Omron CX-Programmer project CP1H_Y20DT_D (CX-Programmer 8.20)
; CP1H-Y20DT-D Demo with R7D-BP01L & NP3-MQ000B

# PLC NewPLC1: CP1H Y

## Global symbols (name address type ; comment)
Acceleration D104 INT  ; Acceleration Hz/4ms
AlarmOutput 0.00 BOOL  ; When the Servo Drive generates an alarm, the output turns OFF.
AlarmResetInput 100.05 BOOL  ; $?St$Bk?_#[117] / ON: Servo alarm status is reset. / Must be ON for 120 ms min.$?St$Bk?_#[117]
101.02 BOOL  ; Origin search 0 (Error counter reset output)
1.03 BOOL  ; Pulse output 0: Origin input signal (open collector)
1.05 BOOL  ; Pulse output 0: Origin proximity input signal
A274.00 BOOL  ; $?St$Bk?_#[118] / Range Comparison Condition Met Flag / Range 1 Comparison Condition Met Flag$?St$Bk?_#[118]
A274.08 BOOL  ; $?St$Bk?_#[119] / Comparison In progress Flag / ON when a comparison operation is being executed for the high-speed counter$?St$Bk?_#[119]
A274.09 BOOL  ; $?St$Bk?_#[120] / Overflow/Underflow Flag / ON when an overflow or underflow has occurred in the high-speed counter’s PV. (Used only when the counting mode is set to Linear Mode)$?St$Bk?_#[120]
A274.10 BOOL  ; $?St$Bk?_#[121] / Count Direction Flag / 0: Decrementing / 1: Incrementing$?St$Bk?_#[121]
A280.00 BOOL  ; $?St$Bk?_#[122] / Accel/Decel Flags / ON when pulses are being output according to an ACC(888) or PLS2(887) instruction and the output frequency is being changed in steps (accelerating or decelerating) / 0: Constant speed / 1: Accelerating or decelerating$?St$Bk?_#[122]
A280.01 BOOL  ; $?St$Bk?_#[123] / Overflow/Underflow Flags / ON when an overflow or underflow has / occurred in the pulse output PV / 0: Normal / 1: Overflow or underflow$?St$Bk?_#[123]
A280.02 BOOL  ; $?St$Bk?_#[124] / Output Amount Set Flags / ON when the number of output pulses has been set with the PULS instruction / 0: No setting / 1: Setting made$?St$Bk?_#[124]
A280.03 BOOL  ; $?St$Bk?_#[125] / Output Completed Flags / ON when the number of output pulses set with the PULS(886)/PLS2(887) instruction has been output / 0: Output not completed / 1: Output completed$?St$Bk?_#[125]
A280.04 BOOL  ; $?St$Bk?_#[126] / Output In-progress Flags / ON when pulses are being output from the pulse output / 0: Stopped / 1: Outputting pulses$?St$Bk?_#[126]
A280.05 BOOL  ; $?St$Bk?_#[127] / No-origin Flags / ON when the origin has not been determined for the pulse output / 0: Origin established / 1: Origin not established$?St$Bk?_#[127]
A280.06 BOOL  ; $?St$Bk?_#[128] / At-origin Flags / ON when the pulse output PV matches / the origin (0) / 0: Not stopped at origin / 1: Stopped at origin$?St$Bk?_#[128]
A280.07 BOOL  ; $?St$Bk?_#[129] / Output Stopped Error Flags / ON when an error occurred while outputting pulses in the origin search function / 0: No error / 1: Stop error occurred$?St$Bk?_#[129]
A392.12 BOOL  ; $?St$Bk?_#[130] / Peripheral Port Communications / Error Flag / ON when a communications error has occurred at the serial port 1$?St$Bk?_#[130]
A444 CHANNEL  ; Stop Error Codes
A526.01 BOOL  ; $?St$Bk?_#[131] / Peripheral Port Restart Bit / Turn this bit ON to restart the serial port 1$?St$Bk?_#[131]
A531.00 BOOL  ; $?St$Bk?_#[132] / Reset Bit / Used for the PV software reset$?St$Bk?_#[132]
A540.00 BOOL  ; $?St$Bk?_#[134] / Reset Bits / The pulse output PV will be cleared when this bit is turned from OFF to ON / 0: Not cleared / 1: Clear PV$?St$Bk?_#[134]
D10 CHANNEL  ; PLS2 Acceleration
D11 CHANNEL  ; PLS2 Deceleration
D12 CHANNEL  ; PLS2 Move Speed
D14 CHANNEL  ; PLS2 Position
H0 CHANNEL  ; PT Control Block
H10 CHANNEL  ; PT Status Block
W0.00 BOOL  ; Reset Alarm
W0.08 BOOL  ; Reset Alarm Required
W10.00 BOOL  ; Servo Alarm
W10.01 BOOL  ; Servo Warning
W11.00 BOOL  ; Origin Servo
W1.00 BOOL  ; Origin Search
W1.01 BOOL  ; Origin Return
W1.02 BOOL  ; Jog Forward
W1.03 BOOL  ; Jog Reverse
W1.04 BOOL  ; Absolute Move
W1.05 BOOL  ; Start Move
W1.06 BOOL  ; Stop Move
W2.00 BOOL  ; Origin Search Latch
W2.01 BOOL  ; Origin Return Latch
W2.04 BOOL  ; Absolute Move One Shot
W3.00 BOOL  ; Origin Search Executing
W3.01 BOOL  ; Origin Return Executing
W3.02 BOOL  ; Jog Forward Executing
W3.03 BOOL  ; Jog Reverse Executing
W3.04 BOOL  ; Absolute Move Enabled
W3.05 BOOL  ; Move Executing
W3.06 BOOL  ; Stop Move
W4.00 BOOL  ; Commanded Position Was Positive
BrakeInterlockOutput 0.04 BOOL  ; Outputs the holding brake timing signals. Release the holding brake when this signal is ON.
Deceleration D105 INT  ; Deceleration Hz/4ms
DeviationCounterResetInput 100.06 BOOL  ; $?St$Bk?_#[138] / Deviation Counter Reset Input in Position Control Mode (when Pn02 is set to 0 or 2). / ON: Pulse commands prohibited and deviation counter cleared. Must be ON for at least 2 ms.$?St$Bk?_#[138]
ElectronicGearSwitchInput 101.00 BOOL  ; $?St$Bk?_#[139] / Electronic Gear Switch Input in Position Control Mode (when Pn02 is set to 0 or 2). / OFF: Electronic Gear Ratio Numerator 1 (Pn46) / ON: Electronic Gear Ratio Numerator 2 (Pn47)$?St$Bk?_#[139]
GainSwitchInput 100.07 BOOL  ; Gain Switch Input in Position Control Mode (when Pn02 is set to 0 or 2) when Zero Speed Designation/Torque Limit Switch (Pn06) is set to 0 or 1.
HighSpeedCounter A270 DINT  ; High-speed Counter PV
JogRunSpeedReference D0 UDINT  ; Jog Run Speed Reference
JogStopSpeedReference D2 UDINT  ; Jog Stop Speed Reference
MoveSpeed D102 DINT  ; Move Speed In Degrees/Second
Position D100 DINT  ; Position In Degrees
PositioningCompletedOutput 0.01 BOOL  ; $?St$Bk?_#[140] / Positioning completed output in Position Control Mode (when Pn02 is set to 0 or 2). / ON: The residual pulses for the deviation counter are within the setting for Positioning Completion Range (Pn60).$?St$Bk?_#[140]
PulseOutput A276 DINT  ; Pulse Output PV
RunCommandInput 100.04 BOOL  ; ON: Servo ON (Starts power to Servomotor.)
WarningOutput 0.05 BOOL  ; The signal selected in the Warning Output Selection (Pn09) is output.

## Program NewProgram1 (cyclic task 0)

### Section Main

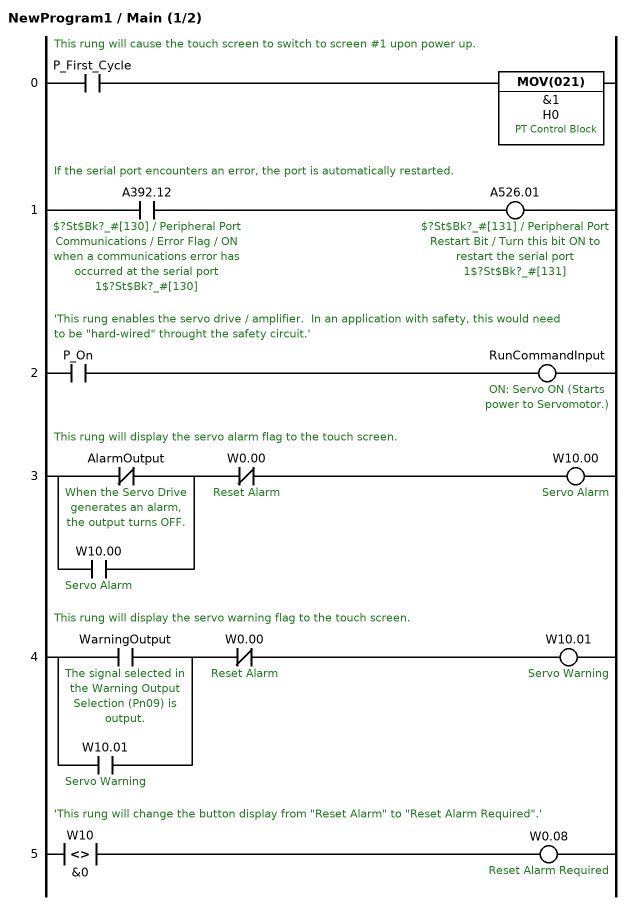
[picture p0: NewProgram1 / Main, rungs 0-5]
; rung 0: This rung will cause the touch screen to switch to screen #1 upon power up.
LD P_First_Cycle
MOV(021) &1 H0  ; PT Control Block
; rung 1: If the serial port encounters an error, the port is automatically restarted.
LD A392.12  ; $?St$Bk?_#[130] / Peripheral Port Communications / Error Flag / ON when a communications error has occurred at the serial port 1$?St$Bk?_#[130]
OUT A526.01  ; $?St$Bk?_#[131] / Peripheral Port Restart Bit / Turn this bit ON to restart the serial port 1$?St$Bk?_#[131]
; rung 2: 'This rung enables the servo drive / amplifier.  In an application with safety, this would need to be "hard-wired" throught the safety circuit.'
LD P_On
OUT RunCommandInput  ; ON: Servo ON (Starts power to Servomotor.)
; rung 3: This rung will display the servo alarm flag to the touch screen.
LDNOT AlarmOutput  ; When the Servo Drive generates an alarm, the output turns OFF.
OR W10.00  ; Servo Alarm
ANDNOT W0.00  ; Reset Alarm
OUT W10.00  ; Servo Alarm
; rung 4: This rung will display the servo warning flag to the touch screen.
LD WarningOutput  ; The signal selected in the Warning Output Selection (Pn09) is output.
OR W10.01  ; Servo Warning
ANDNOT W0.00  ; Reset Alarm
OUT W10.01  ; Servo Warning
; rung 5: 'This rung will change the button display from "Reset Alarm" to "Reset Alarm Required".'
LD<>(305) W10 &0
OUT W0.08  ; Reset Alarm Required

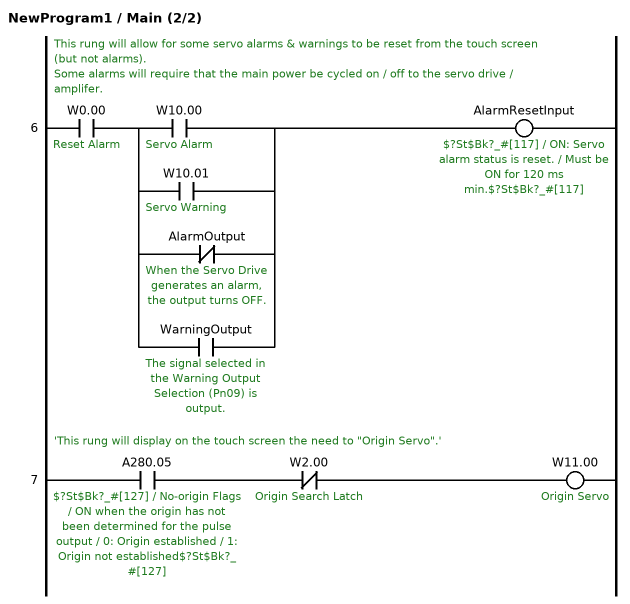
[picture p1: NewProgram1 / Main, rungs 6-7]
; rung 6: This rung will allow for some servo alarms & warnings to be reset from the touch screen (but not alarms). / Some alarms will require that the main power be cycled on / off to the servo drive / amplifer.
LD W0.00  ; Reset Alarm
LD W10.00  ; Servo Alarm
OR W10.01  ; Servo Warning
ORNOT AlarmOutput  ; When the Servo Drive generates an alarm, the output turns OFF.
OR WarningOutput  ; The signal selected in the Warning Output Selection (Pn09) is output.
ANDLD
OUT AlarmResetInput  ; $?St$Bk?_#[117] / ON: Servo alarm status is reset. / Must be ON for 120 ms min.$?St$Bk?_#[117]
; rung 7: 'This rung will display on the touch screen the need to "Origin Servo".'
LD A280.05  ; $?St$Bk?_#[127] / No-origin Flags / ON when the origin has not been determined for the pulse output / 0: Origin established / 1: Origin not established$?St$Bk?_#[127]
ANDNOT W2.00  ; Origin Search Latch
OUT W11.00  ; Origin Servo

### Section Origin

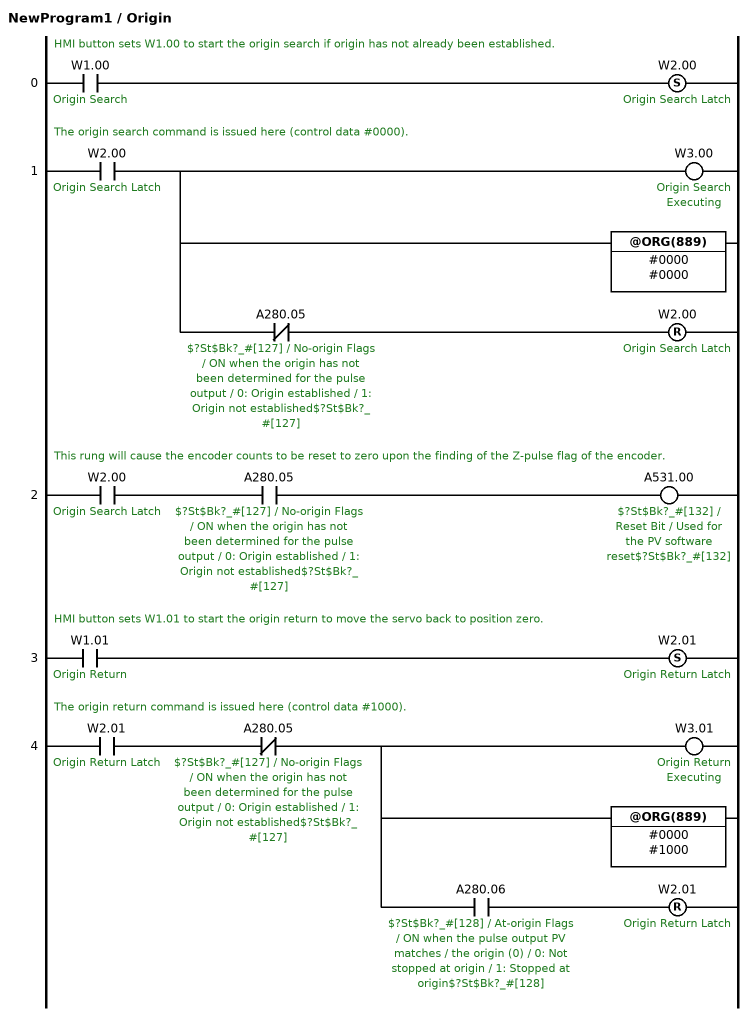
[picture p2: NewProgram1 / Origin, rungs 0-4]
; rung 0: HMI button sets W1.00 to start the origin search if origin has not already been established.
LD W1.00  ; Origin Search
SET W2.00  ; Origin Search Latch
; rung 1: The origin search command is issued here (control data #0000).
LD W2.00  ; Origin Search Latch
OUT W3.00  ; Origin Search Executing
@ORG(889) #0000 #0000
ANDNOT A280.05  ; $?St$Bk?_#[127] / No-origin Flags / ON when the origin has not been determined for the pulse output / 0: Origin established / 1: Origin not established$?St$Bk?_#[127]
RSET W2.00  ; Origin Search Latch
; rung 2: This rung will cause the encoder counts to be reset to zero upon the finding of the Z-pulse flag of the encoder.
LD W2.00  ; Origin Search Latch
AND A280.05  ; $?St$Bk?_#[127] / No-origin Flags / ON when the origin has not been determined for the pulse output / 0: Origin established / 1: Origin not established$?St$Bk?_#[127]
OUT A531.00  ; $?St$Bk?_#[132] / Reset Bit / Used for the PV software reset$?St$Bk?_#[132]
; rung 3: HMI button sets W1.01 to start the origin return to move the servo back to position zero.
LD W1.01  ; Origin Return
SET W2.01  ; Origin Return Latch
; rung 4: The origin return command is issued here (control data #1000).
LD W2.01  ; Origin Return Latch
ANDNOT A280.05  ; $?St$Bk?_#[127] / No-origin Flags / ON when the origin has not been determined for the pulse output / 0: Origin established / 1: Origin not established$?St$Bk?_#[127]
OUT W3.01  ; Origin Return Executing
@ORG(889) #0000 #1000
AND A280.06  ; $?St$Bk?_#[128] / At-origin Flags / ON when the pulse output PV matches / the origin (0) / 0: Not stopped at origin / 1: Stopped at origin$?St$Bk?_#[128]
RSET W2.01  ; Origin Return Latch

### Section Jog

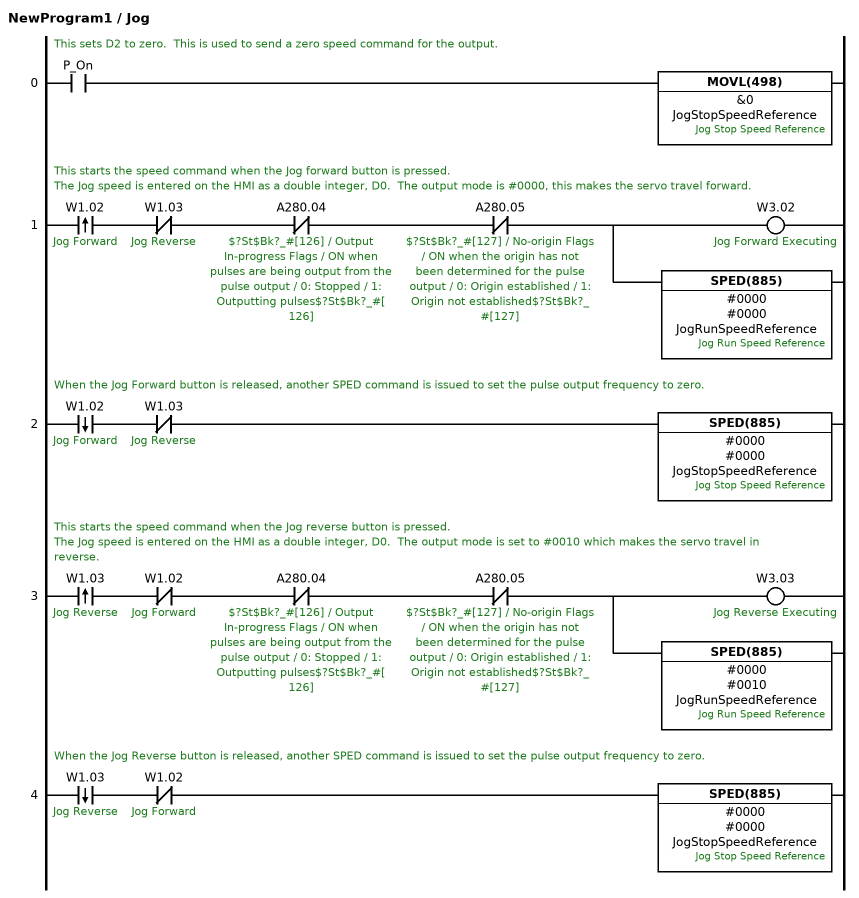
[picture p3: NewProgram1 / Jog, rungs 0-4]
; rung 0: This sets D2 to zero.  This is used to send a zero speed command for the output.
LD P_On
MOVL(498) &0 JogStopSpeedReference  ; Jog Stop Speed Reference
; rung 1: This starts the speed command when the Jog forward button is pressed. / The Jog speed is entered on the HMI as a double integer, D0.  The output mode is #0000, this makes the servo travel forward.
@LD W1.02  ; Jog Forward
ANDNOT W1.03  ; Jog Reverse
ANDNOT A280.04  ; $?St$Bk?_#[126] / Output In-progress Flags / ON when pulses are being output from the pulse output / 0: Stopped / 1: Outputting pulses$?St$Bk?_#[126]
ANDNOT A280.05  ; $?St$Bk?_#[127] / No-origin Flags / ON when the origin has not been determined for the pulse output / 0: Origin established / 1: Origin not established$?St$Bk?_#[127]
OUT W3.02  ; Jog Forward Executing
SPED(885) #0000 #0000 JogRunSpeedReference  ; Jog Run Speed Reference
; rung 2: When the Jog Forward button is released, another SPED command is issued to set the pulse output frequency to zero.
%LD W1.02  ; Jog Forward
ANDNOT W1.03  ; Jog Reverse
SPED(885) #0000 #0000 JogStopSpeedReference  ; Jog Stop Speed Reference
; rung 3: This starts the speed command when the Jog reverse button is pressed. / The Jog speed is entered on the HMI as a double integer, D0.  The output mode is set to #0010 which makes the servo travel in reverse.
@LD W1.03  ; Jog Reverse
ANDNOT W1.02  ; Jog Forward
ANDNOT A280.04  ; $?St$Bk?_#[126] / Output In-progress Flags / ON when pulses are being output from the pulse output / 0: Stopped / 1: Outputting pulses$?St$Bk?_#[126]
ANDNOT A280.05  ; $?St$Bk?_#[127] / No-origin Flags / ON when the origin has not been determined for the pulse output / 0: Origin established / 1: Origin not established$?St$Bk?_#[127]
OUT W3.03  ; Jog Reverse Executing
SPED(885) #0000 #0010 JogRunSpeedReference  ; Jog Run Speed Reference
; rung 4: When the Jog Reverse button is released, another SPED command is issued to set the pulse output frequency to zero.
%LD W1.03  ; Jog Reverse
ANDNOT W1.02  ; Jog Forward
SPED(885) #0000 #0000 JogStopSpeedReference  ; Jog Stop Speed Reference

### Section Move

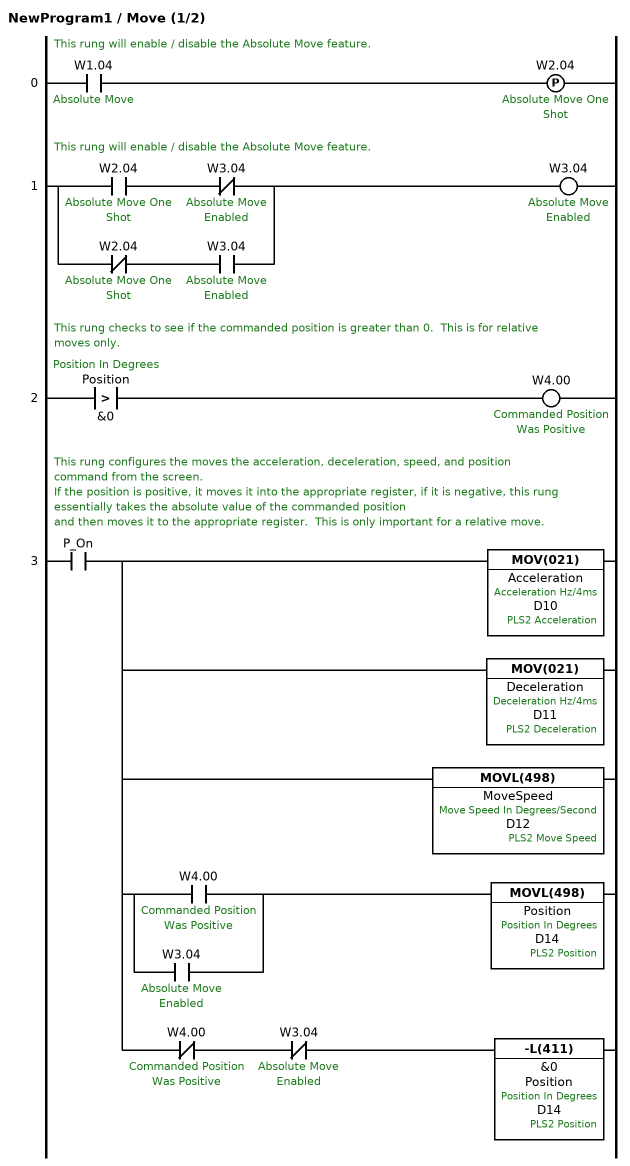
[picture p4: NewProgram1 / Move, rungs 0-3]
; rung 0: This rung will enable / disable the Absolute Move feature.
LD W1.04  ; Absolute Move
DIFU(013) W2.04  ; Absolute Move One Shot
; rung 1: This rung will enable / disable the Absolute Move feature.
LD W2.04  ; Absolute Move One Shot
ANDNOT W3.04  ; Absolute Move Enabled
LDNOT W2.04  ; Absolute Move One Shot
AND W3.04  ; Absolute Move Enabled
ORLD
OUT W3.04  ; Absolute Move Enabled
; rung 2: This rung checks to see if the commanded position is greater than 0.  This is for relative moves only.
LD>SL(323) Position &0  ; Position In Degrees
OUT W4.00  ; Commanded Position Was Positive
; rung 3: This rung configures the moves the acceleration, deceleration, speed, and position command from the screen. / If the position is positive, it moves it into the appropriate register, if it is negative, this rung essentially takes the absolute value of the commanded position / and then moves it to the appropriate register.  This is only important for a relative move.
LD P_On
OUT TR0
MOV(021) Acceleration D10  ; Acceleration Hz/4ms, PLS2 Acceleration
MOV(021) Deceleration D11  ; Deceleration Hz/4ms, PLS2 Deceleration
MOVL(498) MoveSpeed D12  ; Move Speed In Degrees/Second, PLS2 Move Speed
LD W4.00  ; Commanded Position Was Positive
OR W3.04  ; Absolute Move Enabled
ANDLD
MOVL(498) Position D14  ; Position In Degrees, PLS2 Position
LD TR0
ANDNOT W4.00  ; Commanded Position Was Positive
ANDNOT W3.04  ; Absolute Move Enabled
-L(411) &0 Position D14  ; Position In Degrees, PLS2 Position

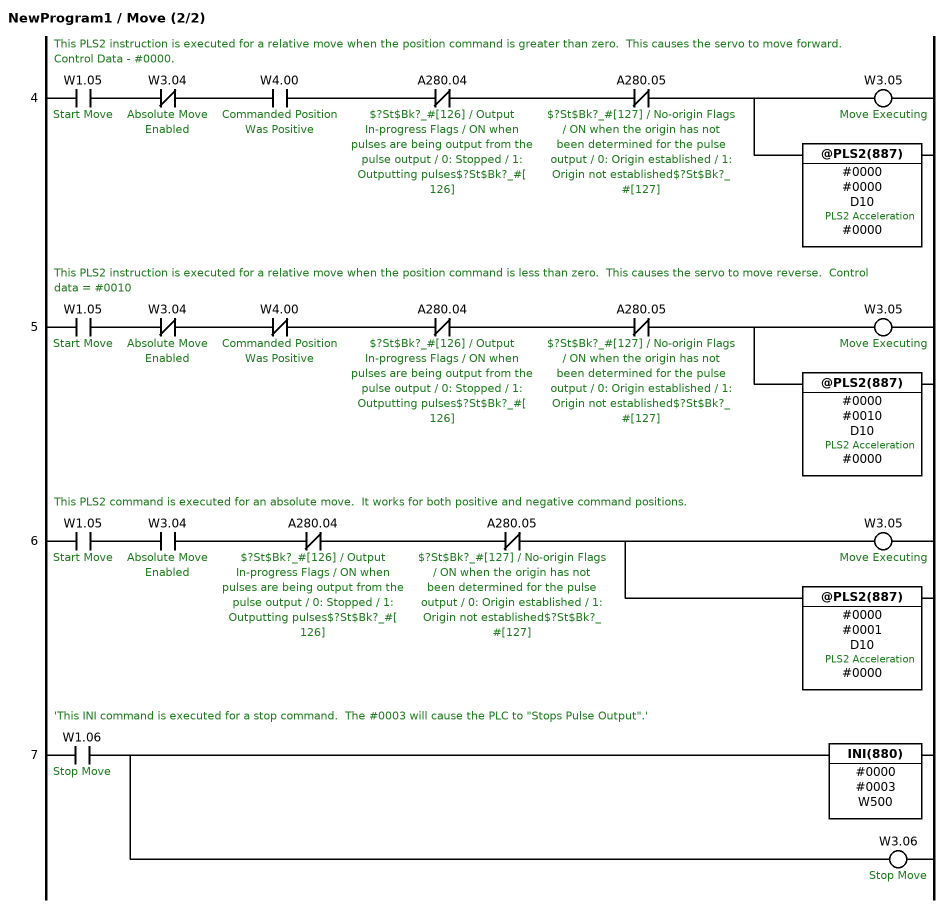
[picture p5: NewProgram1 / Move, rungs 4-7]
; rung 4: This PLS2 instruction is executed for a relative move when the position command is greater than zero.  This causes the servo to move forward.  Control Data - #0000.
LD W1.05  ; Start Move
ANDNOT W3.04  ; Absolute Move Enabled
AND W4.00  ; Commanded Position Was Positive
ANDNOT A280.04  ; $?St$Bk?_#[126] / Output In-progress Flags / ON when pulses are being output from the pulse output / 0: Stopped / 1: Outputting pulses$?St$Bk?_#[126]
ANDNOT A280.05  ; $?St$Bk?_#[127] / No-origin Flags / ON when the origin has not been determined for the pulse output / 0: Origin established / 1: Origin not established$?St$Bk?_#[127]
OUT W3.05  ; Move Executing
@PLS2(887) #0000 #0000 D10 #0000  ; PLS2 Acceleration
; rung 5: This PLS2 instruction is executed for a relative move when the position command is less than zero.  This causes the servo to move reverse.  Control data = #0010
LD W1.05  ; Start Move
ANDNOT W3.04  ; Absolute Move Enabled
ANDNOT W4.00  ; Commanded Position Was Positive
ANDNOT A280.04  ; $?St$Bk?_#[126] / Output In-progress Flags / ON when pulses are being output from the pulse output / 0: Stopped / 1: Outputting pulses$?St$Bk?_#[126]
ANDNOT A280.05  ; $?St$Bk?_#[127] / No-origin Flags / ON when the origin has not been determined for the pulse output / 0: Origin established / 1: Origin not established$?St$Bk?_#[127]
OUT W3.05  ; Move Executing
@PLS2(887) #0000 #0010 D10 #0000  ; PLS2 Acceleration
; rung 6: This PLS2 command is executed for an absolute move.  It works for both positive and negative command positions.
LD W1.05  ; Start Move
AND W3.04  ; Absolute Move Enabled
ANDNOT A280.04  ; $?St$Bk?_#[126] / Output In-progress Flags / ON when pulses are being output from the pulse output / 0: Stopped / 1: Outputting pulses$?St$Bk?_#[126]
ANDNOT A280.05  ; $?St$Bk?_#[127] / No-origin Flags / ON when the origin has not been determined for the pulse output / 0: Origin established / 1: Origin not established$?St$Bk?_#[127]
OUT W3.05  ; Move Executing
@PLS2(887) #0000 #0001 D10 #0000  ; PLS2 Acceleration
; rung 7: 'This INI command is executed for a stop command.  The #0003 will cause the PLC to "Stops Pulse Output".'
LD W1.06  ; Stop Move
INI(880) #0000 #0003 W500
OUT W3.06  ; Stop Move

### Section END
; rung 0
END(001)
